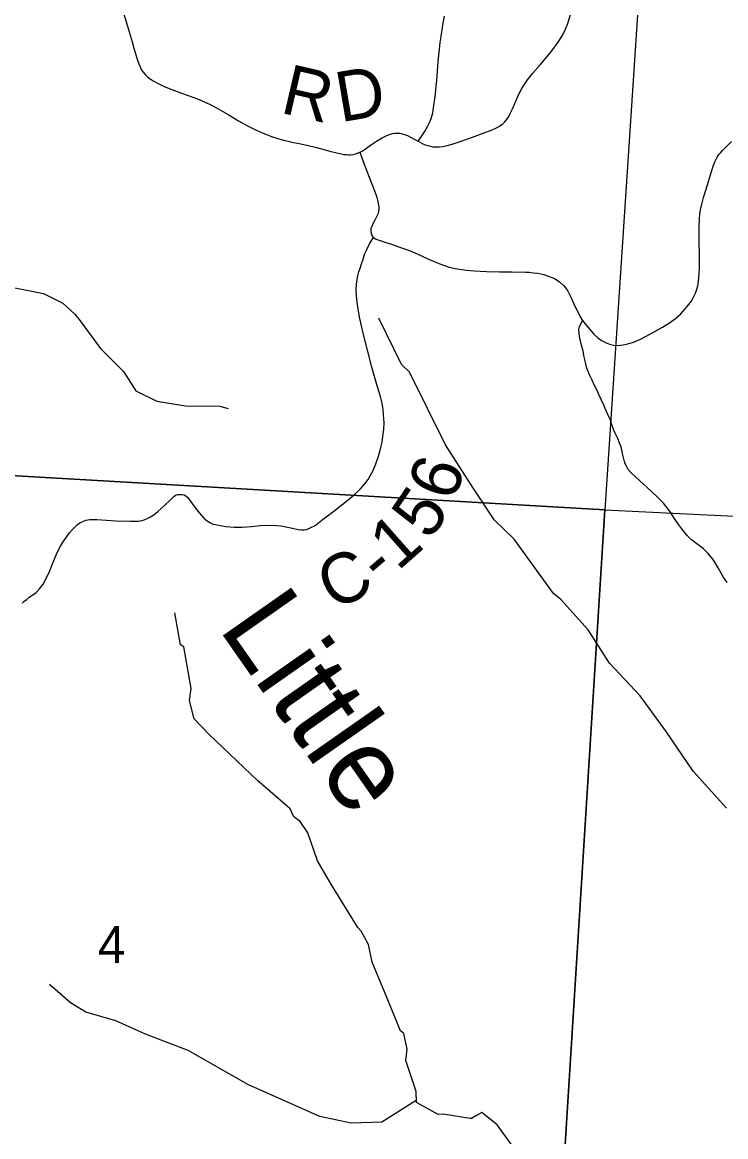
# Model space of a CAD drawing. Extents: x 0 to 34, y 0 to 22.
# Drawn here: x 28.686 to 29.485, y 17.66 to 18.925 of the extents above; entities that cross this region are included whole.
import ezdxf

# ---------------------------------------------------------------- set-up
doc = ezdxf.new("R2010")
doc.units = 0
for name, color, linetype in [('GM_X_County_Road', 7, 'Continuous'), ('GM_X_County_Road_Text', 7, 'Continuous'), ('GM_X_Minor_River', 7, 'Continuous'), ('GM_X_Minor_River_Text', 7, 'Continuous'), ('GM_X_Section', 7, 'Continuous'), ('GM_X_Section_Text', 7, 'Continuous'), ('GM_X_Township_Road', 7, 'Continuous')]:
    doc.layers.add(name, color=color, linetype=linetype)

msp = doc.modelspace()

# ---------------------------------------------------------------- linework, layer by layer
at = {"layer": 'GM_X_County_Road'}
for points in [[(28.7975, 18.9472), (28.8047, 18.9241), (28.8066, 18.9176), (28.811, 18.9027), (28.8131, 18.8955), (28.817, 18.8818), (28.8186, 18.8775), (28.8201, 18.8742), (28.8219, 18.8706), (28.8236, 18.8681), (28.8257, 18.8657), (28.8284, 18.863), (28.8314, 18.8606), (28.8351, 18.8582), (28.8406, 18.8552), (28.8474, 18.852), (28.8561, 18.8485), (28.8725, 18.8425), (28.8811, 18.8393), (28.8879, 18.8367), (28.8923, 18.8348), (28.899, 18.8317), (28.9061, 18.8281), (28.9114, 18.825), (28.92, 18.82), (28.9318, 18.8131), (28.9427, 18.807), (28.9488, 18.8039), (28.9545, 18.8014), (28.9619, 18.7982), (28.9694, 18.7953), (28.9764, 18.793), (28.983, 18.7911), (28.9883, 18.7898), (28.9944, 18.7884), (29.0028, 18.7867), (29.011, 18.7848), (29.0189, 18.783), (29.0263, 18.7812), (29.0358, 18.7786), (29.0434, 18.7766), (29.0486, 18.7754), (29.0516, 18.7749), (29.0546, 18.7746), (29.0569, 18.7745), (29.0591, 18.7745), (29.0622, 18.7748), (29.0647, 18.7754), (29.0672, 18.7762), (29.0696, 18.7772), (29.0725, 18.7787), (29.0761, 18.781), (29.0831, 18.7862), (29.0887, 18.7899), (29.095, 18.7937), (29.1005, 18.7964), (29.1045, 18.7979), (29.1068, 18.7985), (29.1095, 18.7989), (29.1124, 18.7989), (29.1151, 18.7988), (29.1177, 18.7983), (29.1204, 18.7976), (29.1239, 18.7962), (29.1315, 18.7922), (29.1358, 18.79), (29.1414, 18.787), (29.1449, 18.7855), (29.1486, 18.7844), (29.1523, 18.7836), (29.156, 18.7834), (29.1599, 18.7834), (29.1643, 18.7839), (29.1689, 18.7848), (29.1747, 18.7863), (29.1847, 18.7898), (29.1978, 18.7945), (29.2099, 18.799), (29.22, 18.8028), (29.2248, 18.8049), (29.2283, 18.8069), (29.2303, 18.8083), (29.2321, 18.8097), (29.2341, 18.8116), (29.2359, 18.8138), (29.2384, 18.8173), (29.2409, 18.822), (29.2432, 18.8267), (29.2457, 18.8325), (29.249, 18.8404), (29.251, 18.8446), (29.2537, 18.8496), (29.2564, 18.854), (29.2603, 18.8595), (29.2657, 18.8665), (29.2744, 18.8767), (29.2824, 18.8859), (29.2878, 18.8924), (29.2932, 18.8997), (29.2966, 18.9046), (29.2996, 18.9093), (29.3022, 18.9142), (29.3041, 18.9189), (29.3059, 18.9234), (29.3091, 18.9335)], [(29.0696, 18.7772), (29.0724, 18.7698), (29.0784, 18.7538), (29.0857, 18.7353), (29.0881, 18.7284), (29.0893, 18.7247), (29.0901, 18.7215), (29.0909, 18.7173), (29.0912, 18.715), (29.0912, 18.7126), (29.091, 18.7101), (29.0905, 18.7077), (29.0883, 18.7031), (29.0861, 18.6987), (29.0846, 18.6959), (29.0832, 18.6931), (29.0823, 18.6907), (29.082, 18.6879), (29.0824, 18.685), (29.0833, 18.6829), (29.0843, 18.6814), (29.0851, 18.6807), (29.0857, 18.6802), (29.0875, 18.6789), (29.09, 18.6779), (29.0927, 18.677), (29.0994, 18.675), (29.1056, 18.6729), (29.1172, 18.6689), (29.1248, 18.666), (29.1349, 18.6618), (29.1471, 18.6564), (29.1566, 18.6522), (29.1605, 18.6506), (29.1657, 18.6486), (29.1711, 18.6469), (29.1763, 18.6458), (29.1804, 18.645), (29.1854, 18.6443), (29.1908, 18.6435), (29.1998, 18.6427), (29.2064, 18.6422), (29.2134, 18.6419), (29.2282, 18.6414), (29.2425, 18.6414), (29.2581, 18.6413), (29.2621, 18.641), (29.2668, 18.6406), (29.272, 18.6399), (29.2785, 18.6384), (29.2827, 18.6372), (29.2879, 18.6353), (29.2909, 18.6338), (29.2939, 18.6322), (29.2963, 18.6303), (29.301, 18.6261), (29.3032, 18.6234), (29.3059, 18.6195), (29.3086, 18.6145), (29.3112, 18.6088), (29.3143, 18.6018), (29.3175, 18.5953), (29.32, 18.5905), (29.3227, 18.5863), (29.3291, 18.5782), (29.3356, 18.5708), (29.3401, 18.5667), (29.344, 18.5638), (29.3488, 18.5612), (29.3512, 18.5602), (29.3543, 18.5591), (29.3582, 18.5583), (29.3624, 18.5581), (29.3659, 18.5583), (29.3688, 18.5586), (29.3741, 18.5597), (29.3805, 18.5617), (29.3883, 18.5653), (29.4005, 18.5717), (29.4136, 18.5786), (29.4214, 18.5835), (29.4283, 18.5887), (29.4338, 18.5936), (29.4393, 18.5994), (29.4435, 18.6046), (29.4459, 18.608), (29.4478, 18.6114), (29.4509, 18.6174), (29.4526, 18.6219), (29.4536, 18.6255), (29.4545, 18.6308), (29.4549, 18.6351), (29.4553, 18.6448), (29.4553, 18.6574), (29.4551, 18.6798), (29.455, 18.6924), (29.4554, 18.7016), (29.456, 18.707), (29.4567, 18.712), (29.4578, 18.717), (29.4602, 18.7261), (29.4644, 18.7404), (29.4691, 18.7554), (29.471, 18.7615), (29.4729, 18.7663), (29.4742, 18.7688), (29.4757, 18.7716), (29.4776, 18.7746), (29.4792, 18.7766), (29.4817, 18.7794), (29.492, 18.7894)], [(28.6862, 18.2655), (28.6883, 18.2677), (28.6913, 18.2698), (28.6943, 18.2722), (28.6984, 18.2749), (28.7022, 18.2775), (28.706, 18.2816), (28.71, 18.287), (28.7136, 18.2934), (28.7171, 18.3013), (28.7221, 18.314), (28.7259, 18.3229), (28.7298, 18.3302), (28.7336, 18.3364), (28.7399, 18.3453), (28.7432, 18.3491), (28.7487, 18.3542), (28.7517, 18.3565), (28.755, 18.3583), (28.7586, 18.3596), (28.7629, 18.3604), (28.7666, 18.3606), (28.7709, 18.3605), (28.7928, 18.3591), (28.8094, 18.3586), (28.8139, 18.3586), (28.818, 18.3587), (28.8223, 18.3593), (28.8248, 18.36), (28.8281, 18.3614), (28.8319, 18.3633), (28.8362, 18.366), (28.8404, 18.3697), (28.8477, 18.3763), (28.855, 18.3831), (28.858, 18.3861), (28.8605, 18.3879), (28.8627, 18.3888), (28.8653, 18.389), (28.8677, 18.389), (28.87, 18.3884), (28.8722, 18.3872), (28.8743, 18.3854), (28.8759, 18.3833), (28.8789, 18.3788), (28.8831, 18.3734), (28.8877, 18.3676), (28.8927, 18.3621), (28.8964, 18.3589), (28.9, 18.3566), (28.9029, 18.3553), (28.9056, 18.3546), (28.909, 18.3539), (28.9175, 18.3525), (28.9268, 18.3518), (28.9361, 18.3517), (28.9465, 18.3524), (28.9564, 18.3535), (28.9693, 18.354), (28.9755, 18.3537), (28.9805, 18.3532), (28.9877, 18.3519), (28.9931, 18.3506), (28.9995, 18.349), (29.0031, 18.3486), (29.0066, 18.3488), (29.0101, 18.3496), (29.0141, 18.3512), (29.0188, 18.3538), (29.0286, 18.3612), (29.0401, 18.37), (29.0563, 18.3826), (29.0634, 18.3885), (29.0701, 18.395), (29.0754, 18.401), (29.0791, 18.406), (29.0819, 18.4107), (29.0847, 18.4159), (29.088, 18.4235), (29.091, 18.4325), (29.0932, 18.4406), (29.0949, 18.4483), (29.0959, 18.4546), (29.0968, 18.4626), (29.0972, 18.4703), (29.0967, 18.4794), (29.0962, 18.4852), (29.095, 18.4924), (29.093, 18.4999), (29.0894, 18.512), (29.0834, 18.5335), (29.0784, 18.5528), (29.0734, 18.572), (29.0696, 18.5886), (29.0677, 18.5991), (29.0666, 18.607), (29.0659, 18.6144), (29.0656, 18.6213), (29.0658, 18.6275), (29.0667, 18.6328), (29.0676, 18.6371), (29.0686, 18.6416), (29.0699, 18.6458), (29.0714, 18.6506), (29.0733, 18.6558), (29.0755, 18.6623), (29.0775, 18.6668), (29.0808, 18.6733), (29.0832, 18.6775), (29.0843, 18.6794), (29.0851, 18.6807)]]:
    msp.add_lwpolyline(points, dxfattribs=at)
at = {"layer": 'GM_X_Minor_River'}
for points in [[(28.6739, 18.624), (28.7103, 18.6168), (28.7323, 18.6058), (28.7459, 18.5936), (28.751, 18.5874), (28.775, 18.5547), (28.8014, 18.5284), (28.8151, 18.5063), (28.8393, 18.4949), (28.8716, 18.4893), (28.9106, 18.4889), (28.9203, 18.4863)], [(29.486, 18.0327), (29.4484, 18.0749), (29.4176, 18.1199), (29.3882, 18.1603), (29.3534, 18.1975), (29.3292, 18.2351), (29.2978, 18.2695), (29.2897, 18.2766), (29.245, 18.3381), (29.2226, 18.3596), (29.1981, 18.3969), (29.167, 18.445), (29.1261, 18.5275), (29.1172, 18.5362), (29.0913, 18.589)], [(29.1971, 17.6803), (29.1642, 17.6854), (29.1586, 17.685), (29.134, 17.6986), (29.1336, 17.7112), (29.1218, 17.7465), (29.1233, 17.7594), (29.1195, 17.7769), (29.1158, 17.7799), (29.0995, 17.8198), (29.0836, 17.8581), (29.0794, 17.8779), (29.0711, 17.8931), (29.0676, 17.8972), (29.0377, 17.9458), (29.0215, 17.9731), (29.0105, 18.0047), (29.0018, 18.0176), (28.9946, 18.0229), (28.9904, 18.032), (28.9537, 18.0638), (28.8981, 18.1169), (28.8814, 18.134), (28.8761, 18.1548), (28.878, 18.1685), (28.8697, 18.216), (28.8662, 18.2183), (28.8594, 18.2544)], [(29.1336, 17.7009), (29.0946, 17.6765), (29.0597, 17.6753), (29.0244, 17.6829), (28.9431, 17.7186), (28.8748, 17.7576), (28.8262, 17.7762), (28.7926, 17.7913), (28.7585, 17.8012), (28.7411, 17.812), (28.7171, 17.8325)], [(29.501, 17.4324), (29.479, 17.4471), (29.4427, 17.4781), (29.4226, 17.4929), (29.395, 17.5267), (29.392, 17.527), (29.3602, 17.568), (29.3341, 17.5816), (29.3163, 17.5976), (29.3061, 17.6021), (29.3068, 17.6048), (29.2724, 17.621), (29.255, 17.6404), (29.2486, 17.6415), (29.2255, 17.6734), (29.2081, 17.6874), (29.1959, 17.6805), (29.2048, 17.6855)]]:
    msp.add_lwpolyline(points, dxfattribs=at)
at = {"layer": 'GM_X_Section'}
for points in [[(28.356, 19.4486), (29.4164, 19.4097), (29.3481, 18.3713), (28.293, 18.4323)], [(29.3481, 18.3713), (29.2849, 17.3606), (28.2266, 17.4004), (28.2269, 17.4056), (28.2386, 17.5871), (28.2659, 18.0119), (28.293, 18.4323)], [(30.3951, 18.3204), (30.3786, 18.0661), (30.3627, 17.8138), (30.3475, 17.5607), (30.331, 17.3066), (30.2563, 17.3105), (30.177, 17.3146), (30.0998, 17.3186), (30.0187, 17.3227), (29.9382, 17.3269), (29.8591, 17.3308), (29.7781, 17.3351), (29.6912, 17.3401), (29.6192, 17.3436), (29.5335, 17.3481), (29.4508, 17.3523), (29.3695, 17.3565), (29.2849, 17.3606), (29.3481, 18.3713)]]:
    msp.add_lwpolyline(points, close=True, dxfattribs=at)
at = {"layer": 'GM_X_Township_Road'}
for points in [[(29.1358, 18.79), (29.1397, 18.7953), (29.1439, 18.8015), (29.147, 18.8071), (29.1496, 18.8127), (29.1511, 18.8168), (29.1519, 18.8194), (29.1525, 18.8221), (29.1535, 18.8276), (29.1553, 18.8405), (29.1571, 18.859), (29.1587, 18.8798), (29.1601, 18.8943), (29.161, 18.9019), (29.1619, 18.9085), (29.164, 18.9214), (29.1659, 18.9317)], [(29.3485, 18.4864), (29.347, 18.4901), (29.3409, 18.5029), (29.3391, 18.5068), (29.3364, 18.5124), (29.3336, 18.5185), (29.3307, 18.5247), (29.3287, 18.5291), (29.3271, 18.5335), (29.3263, 18.5368), (29.3251, 18.5422), (29.3242, 18.5465), (29.3232, 18.5518), (29.322, 18.5567), (29.3196, 18.5661), (29.3187, 18.571), (29.3185, 18.576), (29.319, 18.5791), (29.3199, 18.5812), (29.3217, 18.5845), (29.3227, 18.5863)], [(29.4869, 18.2891), (29.4843, 18.2926), (29.4823, 18.2954), (29.4803, 18.2989), (29.4765, 18.3056), (29.4729, 18.3119), (29.4705, 18.3153), (29.4672, 18.3197), (29.465, 18.3221), (29.4622, 18.325), (29.4599, 18.3271), (29.4538, 18.3318), (29.4463, 18.3374), (29.4417, 18.3418), (29.4384, 18.3459), (29.4355, 18.3497), (29.432, 18.3543), (29.4261, 18.363), (29.4225, 18.3686), (29.42, 18.3723), (29.4145, 18.3791), (29.4066, 18.387), (29.3961, 18.3968), (29.3878, 18.4043), (29.3775, 18.4137), (29.3745, 18.4172), (29.3724, 18.4208), (29.3712, 18.4235), (29.3703, 18.4262), (29.3682, 18.4352), (29.3671, 18.4396), (29.366, 18.4435), (29.3647, 18.4472), (29.3627, 18.4524), (29.3597, 18.4585), (29.3578, 18.4625), (29.3567, 18.4659), (29.3557, 18.4691), (29.3544, 18.473), (29.3529, 18.4764), (29.3485, 18.4864)]]:
    msp.add_lwpolyline(points, dxfattribs=at)

# ---------------------------------------------------------------- texts
at = {"layer": 'GM_X_County_Road_Text'}
for s, rotation, p in [('R', 346.8887, (28.978, 18.8225)), ('D', 9.6833, (29.0476, 18.8112)), ('6', 71.0324, (29.1764, 18.3795)), ('5', 55.3666, (29.1489, 18.3356)), ('1', 41.5097, (29.1128, 18.3012)), ('C', 26.6261, (29.04, 18.2561)), ('-', 40.4737, (29.0942, 18.2853))]:
    msp.add_text(s, height=0.0568, rotation=rotation, dxfattribs=at).set_placement(p)
at = {"layer": 'GM_X_Minor_River_Text'}
msp.add_text('Little', height=0.09469, rotation=304.9993, dxfattribs=at).set_placement((28.9082, 18.2373))
at = {"layer": 'GM_X_Section_Text'}
msp.add_text('4', height=0.0419, rotation=0, dxfattribs=at).set_placement((28.7722, 17.857))

doc.saveas('drawing.dxf')
